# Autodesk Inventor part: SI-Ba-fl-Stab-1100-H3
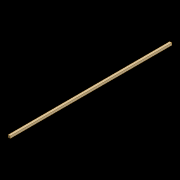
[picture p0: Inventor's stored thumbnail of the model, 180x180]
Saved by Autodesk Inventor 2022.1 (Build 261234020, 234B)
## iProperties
Part Number: SI-Ba-fl-Stab-1100-H3
Material: Allgemein
Document SubType Name: Modellieren
Designer: joachim
Appearance: Vorgabe
Author: joachim
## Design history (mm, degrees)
sketch "Skizze1"
  geometry: L1 (0, 0)-(15, 0); L2 (15, 0)-(15, 15); L3 (15, 15)-(0, 15); L4 (0, 15)-(0, 0)
  constraints: 8 end point, 2 parallel, 1 horizontal, 1 perpendicular
  dimensions: "d0" = 15 distance of L3.end L2.end; "d1" = 15 distance of L2.end L1.end
extrude "Extrusion1" new body sketch "Skizze1" distance "d2" = 1100; taper "d3" = 0 deg
node "Volumenkörper1"
node "Volumenkörper"
node "Flächenkörper"
